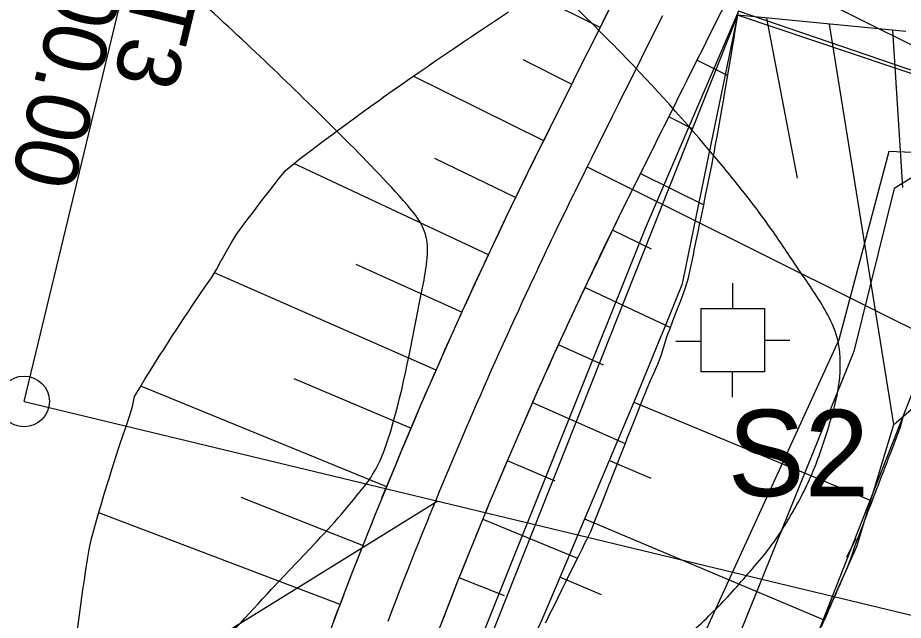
# Model space of a CAD drawing. Extents: x -564043 to -563833, y -1163561 to -1163412.
# Drawn here: x -563904.35 to -563886.88, y -1163493.12 to -1163481.22 of the extents above; entities that cross this region are included whole.
import ezdxf

# ---------------------------------------------------------------- set-up
doc = ezdxf.new("R2010")
doc.units = 0
for name, color, linetype in [('4', 7, 'Continuous'), ('5', 7, 'Continuous'), ('_popis staničení PH3', 7, 'Continuous'), ('_popis staničení T3', 7, 'Continuous'), ('Default', 7, 'Continuous'), ('Line', 7, 'Continuous'), ('Vrstva 24', 7, 'Continuous'), ('Vrstva 25', 7, 'Continuous'), ('Vrstva 26', 7, 'Continuous')]:
    doc.layers.add(name, color=color, linetype=linetype)

msp = doc.modelspace()

# ---------------------------------------------------------------- linework, layer by layer
for p, q in [((-563890.151, -1163481.173), (-563898.85, -1163503.099)), ((-563887.997, -1163491.869), (-563887.811, -1163491.492))]:
    msp.add_line(p, q)
for points in [[(-563898.27, -1163493.54), (-563897.913, -1163492.595), (-563897.753, -1163492.179), (-563897.547, -1163491.654), (-563897.269, -1163490.958), (-563897.171, -1163490.716), (-563896.89, -1163490.033), (-563896.786, -1163489.783), (-563896.391, -1163488.853), (-563895.988, -1163487.927), (-563895.979, -1163487.907), (-563895.575, -1163487.005), (-563895.153, -1163486.088), (-563895.019, -1163485.803), (-563894.721, -1163485.175), (-563894.281, -1163484.266), (-563894.011, -1163483.721), (-563893.834, -1163483.364), (-563893.388, -1163482.469), (-563892.942, -1163481.574), (-563892.496, -1163480.679), (-563892.461, -1163480.609), (-563892.05, -1163479.784), (-563891.777, -1163479.236)], [(-563896.046, -1163493.311), (-563895.888, -1163492.903), (-563895.687, -1163492.389), (-563895.414, -1163491.706), (-563895.318, -1163491.47), (-563895.043, -1163490.8), (-563894.941, -1163490.555), (-563894.554, -1163489.643), (-563894.158, -1163488.736), (-563894.15, -1163488.716), (-563893.754, -1163487.832), (-563893.34, -1163486.933), (-563893.209, -1163486.653), (-563892.917, -1163486.038), (-563892.485, -1163485.147), (-563892.221, -1163484.613), (-563892.044, -1163484.256), (-563891.598, -1163483.361), (-563891.152, -1163482.466), (-563890.706, -1163481.571), (-563890.671, -1163481.5), (-563890.26, -1163480.676), (-563889.986, -1163480.127)], [(-563898.115, -1163493.125), (-563898.048, -1163492.95), (-563897.982, -1163492.775), (-563897.915, -1163492.601), (-563897.913, -1163492.595), (-563897.848, -1163492.426), (-563897.781, -1163492.252), (-563897.753, -1163492.179), (-563897.713, -1163492.078), (-563897.645, -1163491.904), (-563897.577, -1163491.73), (-563897.547, -1163491.654), (-563897.508, -1163491.556), (-563897.439, -1163491.383), (-563897.37, -1163491.209), (-563897.3, -1163491.036), (-563897.23, -1163490.862), (-563897.171, -1163490.716), (-563897.16, -1163490.689), (-563897.089, -1163490.516), (-563897.018, -1163490.343), (-563896.947, -1163490.171), (-563896.89, -1163490.033), (-563896.876, -1163489.998), (-563896.804, -1163489.826), (-563896.786, -1163489.783), (-563896.732, -1163489.653), (-563896.659, -1163489.481), (-563896.586, -1163489.309), (-563896.513, -1163489.137), (-563896.44, -1163488.965), (-563896.391, -1163488.853), (-563896.366, -1163488.794), (-563896.292, -1163488.622), (-563896.217, -1163488.451), (-563896.143, -1163488.279), (-563896.068, -1163488.108), (-563895.992, -1163487.937), (-563895.988, -1163487.927), (-563895.979, -1163487.907), (-563895.917, -1163487.766), (-563895.841, -1163487.596), (-563895.764, -1163487.425), (-563895.688, -1163487.255), (-563895.611, -1163487.085), (-563895.575, -1163487.005), (-563895.533, -1163486.914), (-563895.456, -1163486.744), (-563895.378, -1163486.575), (-563895.3, -1163486.405), (-563895.221, -1163486.235), (-563895.153, -1163486.088), (-563895.142, -1163486.066), (-563895.063, -1163485.897), (-563895.019, -1163485.803), (-563894.984, -1163485.728), (-563894.904, -1163485.559), (-563894.824, -1163485.39), (-563894.743, -1163485.221), (-563894.721, -1163485.175), (-563894.663, -1163485.053), (-563894.582, -1163484.884), (-563894.5, -1163484.716), (-563894.419, -1163484.548), (-563894.337, -1163484.38), (-563894.281, -1163484.266), (-563894.255, -1163484.212), (-563894.172, -1163484.045), (-563894.089, -1163483.877), (-563894.011, -1163483.721), (-563894.006, -1163483.71), (-563893.923, -1163483.544), (-563893.841, -1163483.379), (-563893.834, -1163483.364), (-563893.758, -1163483.213), (-563893.676, -1163483.048), (-563893.593, -1163482.882), (-563893.511, -1163482.716), (-563893.428, -1163482.551), (-563893.388, -1163482.469), (-563893.346, -1163482.385), (-563893.263, -1163482.22), (-563893.181, -1163482.054), (-563893.098, -1163481.889), (-563893.016, -1163481.723), (-563892.942, -1163481.574), (-563892.933, -1163481.557), (-563892.851, -1163481.392), (-563892.768, -1163481.226), (-563892.686, -1163481.061)], [(-563893.939, -1163493.164), (-563893.904, -1163493.093), (-563893.859, -1163493.002), (-563893.779, -1163492.841), (-563893.699, -1163492.679), (-563893.619, -1163492.518), (-563893.539, -1163492.357), (-563893.471, -1163492.221), (-563893.459, -1163492.196), (-563893.379, -1163492.035), (-563893.299, -1163491.873), (-563893.22, -1163491.712), (-563893.157, -1163491.583), (-563893.141, -1163491.55), (-563893.062, -1163491.389), (-563893.042, -1163491.349), (-563892.992, -1163491.224), (-563892.927, -1163491.057), (-563892.862, -1163490.889), (-563892.797, -1163490.722), (-563892.731, -1163490.555), (-563892.689, -1163490.446), (-563892.666, -1163490.388), (-563892.6, -1163490.221), (-563892.535, -1163490.054), (-563892.469, -1163489.886), (-563892.404, -1163489.719), (-563892.338, -1163489.552), (-563892.334, -1163489.542), (-563892.326, -1163489.522), (-563892.272, -1163489.385), (-563892.207, -1163489.218), (-563892.141, -1163489.051), (-563892.075, -1163488.883), (-563892.009, -1163488.716), (-563891.977, -1163488.639), (-563891.939, -1163488.551), (-563891.867, -1163488.386), (-563891.794, -1163488.222), (-563891.722, -1163488.058), (-563891.66, -1163487.888), (-563891.613, -1163487.738), (-563891.606, -1163487.716), (-563891.55, -1163487.543), (-563891.517, -1163487.448), (-563891.489, -1163487.373), (-563891.425, -1163487.205), (-563891.361, -1163487.036), (-563891.297, -1163486.868), (-563891.28, -1163486.821), (-563891.233, -1163486.699), (-563891.169, -1163486.53), (-563891.117, -1163486.356), (-563891.079, -1163486.174), (-563891.042, -1163485.992), (-563891.016, -1163485.868), (-563891.004, -1163485.81), (-563890.967, -1163485.627), (-563890.929, -1163485.445), (-563890.893, -1163485.274), (-563890.891, -1163485.262), (-563890.852, -1163485.075), (-563890.813, -1163484.888), (-563890.81, -1163484.871), (-563890.774, -1163484.7), (-563890.736, -1163484.513), (-563890.698, -1163484.325), (-563890.66, -1163484.137), (-563890.624, -1163483.948), (-563890.607, -1163483.855), (-563890.59, -1163483.759), (-563890.556, -1163483.569), (-563890.522, -1163483.379), (-563890.488, -1163483.189), (-563890.455, -1163482.999), (-563890.425, -1163482.828), (-563890.422, -1163482.809), (-563890.389, -1163482.619), (-563890.356, -1163482.428), (-563890.324, -1163482.238), (-563890.291, -1163482.047), (-563890.259, -1163481.856), (-563890.25, -1163481.799), (-563890.227, -1163481.666), (-563890.196, -1163481.475), (-563890.164, -1163481.284), (-563890.133, -1163481.092)], [(-563903.174, -1163493.306), (-563903.149, -1163493.108), (-563903.123, -1163492.909), (-563903.117, -1163492.865), (-563903.096, -1163492.711), (-563903.095, -1163492.703), (-563903.068, -1163492.513), (-563903.039, -1163492.315), (-563903.009, -1163492.117), (-563902.977, -1163491.919), (-563902.957, -1163491.796), (-563902.945, -1163491.722), (-563902.905, -1163491.528), (-563902.853, -1163491.338), (-563902.799, -1163491.148), (-563902.745, -1163490.959), (-563902.69, -1163490.77), (-563902.688, -1163490.764), (-563902.633, -1163490.581), (-563902.576, -1163490.393), (-563902.552, -1163490.314), (-563902.517, -1163490.205), (-563902.458, -1163490.017), (-563902.398, -1163489.83), (-563902.371, -1163489.748), (-563902.336, -1163489.643), (-563902.274, -1163489.457), (-563902.21, -1163489.27), (-563902.146, -1163489.084), (-563902.089, -1163488.895), (-563902.058, -1163488.729), (-563902.049, -1163488.699), (-563901.946, -1163488.529), (-563901.843, -1163488.359), (-563901.738, -1163488.19), (-563901.654, -1163488.055), (-563901.633, -1163488.021), (-563901.527, -1163487.852), (-563901.5, -1163487.811), (-563901.42, -1163487.684), (-563901.312, -1163487.517), (-563901.203, -1163487.35), (-563901.093, -1163487.184), (-563900.983, -1163487.018), (-563900.91, -1163486.909), (-563900.871, -1163486.852), (-563900.759, -1163486.687), (-563900.646, -1163486.523), (-563900.532, -1163486.359), (-563900.431, -1163486.189), (-563900.337, -1163486.017), (-563900.331, -1163486.007), (-563900.32, -1163485.987), (-563900.241, -1163485.846), (-563900.144, -1163485.675), (-563900.042, -1163485.506), (-563899.926, -1163485.344), (-563899.806, -1163485.184), (-563899.75, -1163485.11), (-563899.685, -1163485.024), (-563899.563, -1163484.865), (-563899.44, -1163484.707), (-563899.317, -1163484.549), (-563899.193, -1163484.392), (-563899.084, -1163484.255), (-563899.068, -1163484.235), (-563898.901, -1163484.098), (-563898.805, -1163484.023), (-563898.727, -1163483.964), (-563898.553, -1163483.832), (-563898.379, -1163483.7), (-563898.203, -1163483.568), (-563898.155, -1163483.532), (-563898.028, -1163483.437), (-563897.851, -1163483.307), (-563897.675, -1163483.178), (-563897.498, -1163483.049), (-563897.32, -1163482.921), (-563897.199, -1163482.834), (-563897.142, -1163482.793), (-563896.963, -1163482.666), (-563896.785, -1163482.54), (-563896.617, -1163482.422), (-563896.606, -1163482.415), (-563896.432, -1163482.295), (-563896.257, -1163482.175), (-563896.242, -1163482.164), (-563896.083, -1163482.055), (-563895.908, -1163481.936), (-563895.732, -1163481.816), (-563895.556, -1163481.697), (-563895.38, -1163481.578), (-563895.293, -1163481.52), (-563895.203, -1163481.46), (-563895.026, -1163481.341), (-563894.849, -1163481.223), (-563894.671, -1163481.105)], [(-563897.048, -1163493.132), (-563896.982, -1163492.959), (-563896.979, -1163492.953), (-563896.915, -1163492.786), (-563896.849, -1163492.614), (-563896.82, -1163492.541), (-563896.781, -1163492.441), (-563896.714, -1163492.269), (-563896.646, -1163492.097), (-563896.617, -1163492.021), (-563896.578, -1163491.925), (-563896.51, -1163491.753), (-563896.442, -1163491.581), (-563896.373, -1163491.409), (-563896.303, -1163491.238), (-563896.245, -1163491.093), (-563896.234, -1163491.066), (-563896.164, -1163490.895), (-563896.094, -1163490.724), (-563896.023, -1163490.553), (-563895.967, -1163490.416), (-563895.952, -1163490.382), (-563895.881, -1163490.211), (-563895.863, -1163490.169), (-563895.81, -1163490.04), (-563895.738, -1163489.87), (-563895.666, -1163489.7), (-563895.593, -1163489.529), (-563895.521, -1163489.359), (-563895.473, -1163489.248), (-563895.447, -1163489.189), (-563895.374, -1163489.019), (-563895.3, -1163488.85), (-563895.226, -1163488.68), (-563895.152, -1163488.511), (-563895.078, -1163488.342), (-563895.073, -1163488.331), (-563895.064, -1163488.311), (-563895.003, -1163488.172), (-563894.927, -1163488.003), (-563894.852, -1163487.835), (-563894.776, -1163487.666), (-563894.7, -1163487.497), (-563894.664, -1163487.419), (-563894.623, -1163487.329), (-563894.546, -1163487.16), (-563894.469, -1163486.992), (-563894.392, -1163486.824), (-563894.314, -1163486.656), (-563894.246, -1163486.51), (-563894.236, -1163486.489), (-563894.158, -1163486.321), (-563894.114, -1163486.228), (-563894.079, -1163486.154), (-563894, -1163485.986), (-563893.921, -1163485.819), (-563893.841, -1163485.652), (-563893.819, -1163485.606), (-563893.761, -1163485.485), (-563893.681, -1163485.319), (-563893.601, -1163485.152), (-563893.52, -1163484.986), (-563893.439, -1163484.819), (-563893.383, -1163484.706), (-563893.357, -1163484.653), (-563893.275, -1163484.487), (-563893.193, -1163484.322), (-563893.116, -1163484.167), (-563893.111, -1163484.156), (-563893.028, -1163483.99), (-563892.946, -1163483.825), (-563892.939, -1163483.81), (-563892.863, -1163483.659), (-563892.781, -1163483.494), (-563892.698, -1163483.328), (-563892.616, -1163483.162), (-563892.533, -1163482.997), (-563892.493, -1163482.915), (-563892.451, -1163482.831), (-563892.368, -1163482.666), (-563892.286, -1163482.5), (-563892.203, -1163482.335), (-563892.121, -1163482.169), (-563892.047, -1163482.02), (-563892.038, -1163482.003), (-563891.956, -1163481.838), (-563891.873, -1163481.672), (-563891.791, -1163481.507), (-563891.708, -1163481.341), (-563891.626, -1163481.175)], [(-563895.982, -1163493.146), (-563895.916, -1163492.975), (-563895.888, -1163492.903), (-563895.85, -1163492.804), (-563895.783, -1163492.634), (-563895.716, -1163492.463), (-563895.687, -1163492.389), (-563895.649, -1163492.293), (-563895.581, -1163492.123), (-563895.513, -1163491.953), (-563895.445, -1163491.783), (-563895.376, -1163491.613), (-563895.318, -1163491.47), (-563895.308, -1163491.443), (-563895.238, -1163491.274), (-563895.169, -1163491.104), (-563895.099, -1163490.935), (-563895.043, -1163490.8), (-563895.029, -1163490.766), (-563894.958, -1163490.597), (-563894.941, -1163490.555), (-563894.888, -1163490.428), (-563894.817, -1163490.259), (-563894.745, -1163490.09), (-563894.673, -1163489.922), (-563894.601, -1163489.753), (-563894.554, -1163489.643), (-563894.529, -1163489.585), (-563894.456, -1163489.417), (-563894.384, -1163489.249), (-563894.31, -1163489.081), (-563894.237, -1163488.913), (-563894.163, -1163488.746), (-563894.158, -1163488.736), (-563894.15, -1163488.716), (-563894.089, -1163488.578), (-563894.014, -1163488.411), (-563893.939, -1163488.244), (-563893.864, -1163488.077), (-563893.789, -1163487.91), (-563893.754, -1163487.832), (-563893.713, -1163487.743), (-563893.637, -1163487.576), (-563893.561, -1163487.41), (-563893.484, -1163487.244), (-563893.407, -1163487.077), (-563893.34, -1163486.933), (-563893.33, -1163486.911), (-563893.252, -1163486.746), (-563893.209, -1163486.653), (-563893.174, -1163486.58), (-563893.096, -1163486.414), (-563893.018, -1163486.249), (-563892.939, -1163486.083), (-563892.917, -1163486.038), (-563892.86, -1163485.918), (-563892.78, -1163485.753), (-563892.701, -1163485.588), (-563892.621, -1163485.423), (-563892.54, -1163485.259), (-563892.485, -1163485.147), (-563892.46, -1163485.094), (-563892.379, -1163484.93), (-563892.297, -1163484.766), (-563892.221, -1163484.613), (-563892.216, -1163484.602), (-563892.133, -1163484.436), (-563892.051, -1163484.271), (-563892.044, -1163484.256), (-563891.968, -1163484.105), (-563891.886, -1163483.94), (-563891.803, -1163483.774), (-563891.721, -1163483.608), (-563891.638, -1163483.443), (-563891.598, -1163483.361), (-563891.556, -1163483.277), (-563891.473, -1163483.112), (-563891.391, -1163482.946), (-563891.308, -1163482.78), (-563891.226, -1163482.615), (-563891.152, -1163482.466), (-563891.143, -1163482.449), (-563891.061, -1163482.284), (-563890.978, -1163482.118), (-563890.896, -1163481.953), (-563890.813, -1163481.787), (-563890.731, -1163481.621), (-563890.706, -1163481.571), (-563890.648, -1163481.456), (-563890.566, -1163481.29), (-563890.483, -1163481.125)], [(-563878.137, -1163496.97), (-563876.837, -1163490), (-563879.296, -1163487.066), (-563881.987, -1163484.651), (-563882.119, -1163484.582), (-563882.455, -1163484.408), (-563883.788, -1163483.304), (-563883.864, -1163483.279), (-563884.159, -1163483.181), (-563884.226, -1163483.159), (-563884.302, -1163483.134), (-563884.34, -1163483.121), (-563884.386, -1163483.106), (-563884.482, -1163483.074), (-563884.592, -1163483.038), (-563884.718, -1163482.996), (-563884.865, -1163482.947), (-563884.978, -1163482.91), (-563885.376, -1163482.786), (-563885.4, -1163482.777), (-563885.486, -1163482.747), (-563885.596, -1163482.707), (-563890.151, -1163481.173)], [(-563882.19, -1163496.364), (-563880.778, -1163492.835), (-563880.808, -1163489.502), (-563880.527, -1163488.546), (-563880.34, -1163487.91), (-563881.995, -1163486.424), (-563882.215, -1163486.31), (-563882.772, -1163486.021), (-563884.984, -1163484.19), (-563885.111, -1163484.148), (-563885.233, -1163484.108), (-563885.348, -1163484.069), (-563885.478, -1163484.026), (-563885.544, -1163484.004), (-563885.623, -1163483.978), (-563885.788, -1163483.923), (-563887.164, -1163483.863), (-563888.153, -1163487.579), (-563890.867, -1163493.518)], [(-563889.53, -1163495.82), (-563888.841, -1163493.998), (-563888.841, -1163493.998), (-563888.841, -1163493.998), (-563887.797, -1163491.659), (-563887.07, -1163489.251), (-563885.406, -1163487.811), (-563884.336, -1163488.791), (-563884.336, -1163488.791), (-563884.336, -1163488.791), (-563883.356, -1163488.989), (-563882.375, -1163489.186), (-563882.009, -1163489.26), (-563881.395, -1163489.384), (-563880.687, -1163489.526), (-563880.415, -1163489.581), (-563879.434, -1163489.779), (-563879.009, -1163490.8), (-563878.655, -1163493.506)], [(-563886.679, -1163488.563), (-563889.53, -1163495.82)], [(-563886.875, -1163489.052), (-563886.889, -1163489.104), (-563886.908, -1163489.177), (-563886.916, -1163489.206), (-563886.923, -1163489.229), (-563886.938, -1163489.287), (-563886.982, -1163489.414), (-563887, -1163489.464), (-563887.048, -1163489.589), (-563887.067, -1163489.639), (-563887.115, -1163489.763), (-563887.134, -1163489.813), (-563887.183, -1163489.938), (-563887.201, -1163489.987), (-563887.239, -1163490.083), (-563887.253, -1163490.12), (-563887.264, -1163490.149), (-563887.268, -1163490.16), (-563887.317, -1163490.287), (-563887.335, -1163490.334), (-563887.372, -1163490.43), (-563887.386, -1163490.466), (-563887.398, -1163490.497), (-563887.402, -1163490.508), (-563887.451, -1163490.636), (-563887.469, -1163490.682), (-563887.518, -1163490.811), (-563887.535, -1163490.856), (-563887.585, -1163490.985), (-563887.602, -1163491.03), (-563887.651, -1163491.16), (-563887.668, -1163491.204), (-563887.718, -1163491.335), (-563887.734, -1163491.379), (-563887.784, -1163491.509), (-563887.801, -1163491.552), (-563887.849, -1163491.684), (-563887.865, -1163491.727), (-563887.879, -1163491.77), (-563887.924, -1163491.903), (-563887.927, -1163491.911), (-563887.935, -1163491.936), (-563887.948, -1163491.97), (-563887.99, -1163492.08), (-563888.048, -1163492.212), (-563888.066, -1163492.252), (-563888.109, -1163492.35), (-563888.121, -1163492.379), (-563888.136, -1163492.413), (-563888.14, -1163492.423), (-563888.199, -1163492.556), (-563888.215, -1163492.594), (-563888.274, -1163492.728), (-563888.29, -1163492.765), (-563888.313, -1163492.818), (-563888.319, -1163492.832), (-563888.355, -1163492.915), (-563888.364, -1163492.937), (-563888.424, -1163493.073), (-563888.439, -1163493.108), (-563888.499, -1163493.245)]]:
    msp.add_lwpolyline(points)
for points in [[(-563900.324, -1163505.882), (-563892.678, -1163503.006), (-563888.735, -1163501.906), (-563886.271, -1163502.018), (-563883.536, -1163500.684), (-563878.095, -1163497.234), (-563876.621, -1163489.849), (-563880.163, -1163485.998), (-563881.977, -1163484.515), (-563883.765, -1163483.269), (-563890.133, -1163481.092), (-563891.974, -1163485.382), (-563895.143, -1163493.304), (-563898.704, -1163502.458), (-563900.439, -1163505.855)], [(-563887.058, -1163484.593), (-563887.855, -1163487.81), (-563890.21, -1163493.633), (-563891.581, -1163498.253), (-563891.461, -1163499.576), (-563890.275, -1163499.82), (-563886.599, -1163499.649), (-563882.84, -1163497.558), (-563881.049, -1163492.941), (-563880.784, -1163487.979), (-563884.81, -1163484.679), (-563886.418, -1163484.198)]]:
    msp.add_lwpolyline(points, close=True)
at = {"layer": '4'}
for p, q in [((-563890.245, -1163486.961), (-563890.245, -1163486.461)), ((-563890.87, -1163487.611), (-563891.37, -1163487.611)), ((-563889.62, -1163487.586), (-563889.12, -1163487.586)), ((-563890.258, -1163488.211), (-563890.258, -1163488.711))]:
    msp.add_line(p, q, dxfattribs=at)
msp.add_lwpolyline([(-563890.87, -1163486.961), (-563889.62, -1163486.961), (-563889.62, -1163488.211), (-563890.87, -1163488.211)], close=True, dxfattribs=at)
at = {"layer": '5'}
msp.add_line((-563904.23, -1163488.796), (-563873.359, -1163496.24), dxfattribs=at)
at = {"layer": '_popis staničení PH3'}
for points in [[(-563890.882, -1163479.681), (-563870.022, -1163490.074)], [(-563893.116, -1163484.167), (-563871.756, -1163494.81)]]:
    msp.add_lwpolyline(points, dxfattribs=at)
at = {"layer": '_popis staničení T3'}
for points in [[(-563904.23, -1163488.796), (-563901.539, -1163477.637)], [(-563896.064, -1163490.765), (-563901.13, -1163493.9), (-563906.969, -1163518.117)]]:
    msp.add_lwpolyline(points, dxfattribs=at)
msp.add_circle((-563904.23, -1163488.796), 0.5, dxfattribs=at)
at = {"layer": 'Default'}
msp.add_lwpolyline([(-563886.832, -1163481.493), (-563890.151, -1163481.173), (-563890.761, -1163484.133), (-563891.23, -1163486.411), (-563891.248, -1163486.496), (-563891.655, -1163487.489), (-563891.658, -1163487.497), (-563891.845, -1163487.951), (-563892.101, -1163488.575), (-563892.249, -1163488.936), (-563893.249, -1163491.302), (-563893.527, -1163491.96), (-563894.011, -1163493.107), (-563894.298, -1163493.726)], dxfattribs=at)
at = {"layer": 'Line'}
for p, q in [((-563892.862, -1163481.413), (-563894.158, -1163480.767)), ((-563889.579, -1163481.228), (-563888.976, -1163484.391)), ((-563887.07, -1163489.251), (-563888.335, -1163481.348)), ((-563887.091, -1163481.468), (-563886.894, -1163484.572)), ((-563894.39, -1163482.049), (-563893.419, -1163482.532)), ((-563890.949, -1163482.059), (-563890.345, -1163482.36)), ((-563893.976, -1163483.651), (-563896.552, -1163482.378)), ((-563891.038, -1163483.412), (-563891.506, -1163483.178)), ((-563896.131, -1163483.997), (-563894.527, -1163484.773)), ((-563895.065, -1163485.902), (-563898.905, -1163484.101)), ((-563892.064, -1163484.297), (-563890.819, -1163484.914)), ((-563891.847, -1163485.792), (-563892.617, -1163485.418)), ((-563897.68, -1163486.088), (-563895.588, -1163487.037)), ((-563896.097, -1163488.179), (-563900.473, -1163486.259)), ((-563893.158, -1163486.545), (-563891.476, -1163487.338)), ((-563892.797, -1163488.083), (-563893.683, -1163487.679)), ((-563898.903, -1163488.346), (-563896.592, -1163489.326)), ((-563897.073, -1163490.48), (-563901.924, -1163488.492)), ((-563894.194, -1163488.82), (-563892.367, -1163489.625)), ((-563892.197, -1163488.809), (-563887.537, -1163490.746)), ((-563893.752, -1163490.367), (-563894.691, -1163489.967)), ((-563891.855, -1163490.315), (-563892.672, -1163489.966)), ((-563899.953, -1163490.686), (-563897.541, -1163491.639)), ((-563897.992, -1163492.805), (-563902.755, -1163490.993)), ((-563895.174, -1163491.12), (-563893.307, -1163491.888)), ((-563893.169, -1163491.112), (-563888.462, -1163493.101)), ((-563894.747, -1163492.634), (-563895.642, -1163492.279)), ((-563892.838, -1163492.613), (-563893.655, -1163492.264))]:
    msp.add_line(p, q, dxfattribs=at)
at = {"layer": 'Vrstva 24'}
for points in [[(-563903.419, -1163497.029), (-563902.125, -1163495.59), (-563900.744, -1163494.039), (-563899.345, -1163492.505), (-563898.448, -1163491.553), (-563897.897, -1163490.941), (-563897.635, -1163490.622), (-563897.383, -1163490.29), (-563897.001, -1163489.401), (-563896.398, -1163486.71), (-563896.305, -1163486.212), (-563896.276, -1163485.962), (-563896.268, -1163485.713), (-563896.394, -1163485.294), (-563896.666, -1163484.924), (-563897.969, -1163483.548), (-563899.309, -1163482.237), (-563900.743, -1163480.898), (-563903.659, -1163478.289), (-563907.403, -1163474.951), (-563909.511, -1163473.024), (-563914.099, -1163468.742), (-563916.271, -1163466.637)], [(-563866.364, -1163497.311), (-563866.075, -1163496.511), (-563865.895, -1163495.533), (-563865.845, -1163494.553), (-563865.947, -1163493.507), (-563866.272, -1163492.388), (-563866.563, -1163491.699), (-563866.868, -1163491.02), (-563867.192, -1163490.352), (-563867.536, -1163489.691), (-563869.125, -1163486.92), (-563869.85, -1163485.772), (-563870.624, -1163484.653), (-563871.666, -1163483.346), (-563872.824, -1163482.142), (-563874.562, -1163480.618), (-563875.472, -1163479.893), (-563878.363, -1163477.556), (-563882.755, -1163474.046), (-563884.234, -1163472.969), (-563885.61, -1163472.026), (-563886.998, -1163471.1), (-563889.83, -1163469.34), (-563892.347, -1163467.891)]]:
    msp.add_spline(points, degree=3, dxfattribs=at)
at = {"layer": 'Vrstva 25'}
msp.add_spline([(-563905.141, -1163510.37), (-563904.922, -1163510.229), (-563901.706, -1163508.177), (-563898.297, -1163505.868), (-563895.6, -1163504.013), (-563893.249, -1163502.324), (-563892.081, -1163501.469), (-563890.919, -1163500.608), (-563889.757, -1163499.746), (-563888.589, -1163498.892), (-563887.491, -1163498.145), (-563886.364, -1163497.441), (-563885.229, -1163496.747), (-563884.107, -1163496.03), (-563883.48, -1163495.59), (-563883.181, -1163495.349), (-563882.893, -1163495.092), (-563882.209, -1163494.336), (-563881.626, -1163493.502), (-563881.193, -1163492.783), (-563880.36, -1163491.213), (-563880.004, -1163490.417), (-563879.711, -1163489.616), (-563879.829, -1163489.186), (-563884.789, -1163483.345)], degree=3, dxfattribs=at)
at = {"layer": 'Vrstva 26'}
for points in [[(-563873.45, -1163489.454), (-563873.727, -1163488.976), (-563874.776, -1163487.436), (-563876.784, -1163484.893), (-563881.14, -1163480.242), (-563883.664, -1163478.013), (-563887.513, -1163475.075), (-563890.545, -1163473.024), (-563896.225, -1163469.436), (-563897.371, -1163468.706), (-563897.941, -1163468.337), (-563899.477, -1163467.352), (-563904.895, -1163463.746), (-563905.311, -1163463.453)], [(-563904.255, -1163504.408), (-563901.932, -1163502.584), (-563900.774, -1163501.667), (-563899.621, -1163500.744), (-563898.128, -1163499.495), (-563896.658, -1163498.219), (-563892.051, -1163494.217), (-563891.058, -1163493.351), (-563890.3, -1163492.602), (-563889.946, -1163492.201), (-563889.6, -1163491.789), (-563889.274, -1163491.333), (-563889.128, -1163491.092), (-563888.986, -1163490.845), (-563888.757, -1163490.393), (-563888.565, -1163489.929), (-563888.402, -1163489.454), (-563888.258, -1163488.97), (-563888.179, -1163488.634), (-563888.132, -1163488.29), (-563888.126, -1163487.946), (-563888.168, -1163487.609), (-563888.372, -1163487.087), (-563888.888, -1163486.275), (-563889.418, -1163485.493), (-563889.974, -1163484.737), (-563890.569, -1163484.004), (-563892.45, -1163481.915), (-563894.839, -1163479.601), (-563896.896, -1163477.665), (-563897.939, -1163476.713), (-563899, -1163475.779), (-563899.292, -1163475.563), (-563900.233, -1163474.949)], [(-563906.28, -1163515.803), (-563905.884, -1163515.571), (-563902.883, -1163513.741), (-563899.929, -1163512.038), (-563897.928, -1163511.018), (-563895.553, -1163509.778), (-563893.055, -1163508.246), (-563892.353, -1163507.782), (-563891.657, -1163507.311), (-563890.96, -1163506.841), (-563890.257, -1163506.379), (-563888.16, -1163505.094), (-563886.21, -1163504.031), (-563880.965, -1163501.085), (-563878.454, -1163499.578), (-563877.23, -1163498.772), (-563876.032, -1163497.922), (-563874.901, -1163496.941), (-563873.614, -1163495.651), (-563873.276, -1163495.107), (-563873.154, -1163494.587), (-563873.048, -1163494.066), (-563872.865, -1163493.019), (-563872.827, -1163492.778)]]:
    msp.add_spline(points, degree=3, dxfattribs=at)

# ---------------------------------------------------------------- texts
at = {"layer": '4'}
msp.add_text('S2', height=1.7047, rotation=360, dxfattribs=at).set_placement((-563890.346, -1163490.666))
at = {"layer": '_popis staničení T3'}
for s, p in [('0+000.00', (-563902.844, -1163477.573)), ('ZU T3 ', (-563901.386, -1163477.925))]:
    msp.add_text(s, height=1.25, rotation=256.4433, dxfattribs=at).set_placement(p)

doc.saveas('drawing.dxf')
